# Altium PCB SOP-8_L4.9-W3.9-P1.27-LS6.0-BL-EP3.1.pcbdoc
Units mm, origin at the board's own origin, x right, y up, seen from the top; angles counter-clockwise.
Board outline 18.03 x 20.04 mm, 2 copper layers (Top Layer, Bottom Layer), stack 0 mm thick; 1 components, 0 nets, 9 pads, 4 vias.
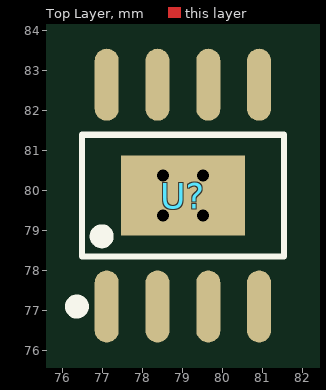
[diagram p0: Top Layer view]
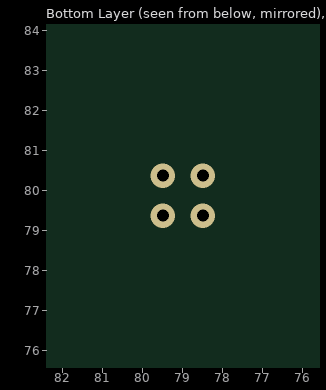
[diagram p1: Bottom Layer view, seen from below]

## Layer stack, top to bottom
Top Layer: signal copper (thickness not stored)
Bottom Layer: signal copper (thickness not stored)

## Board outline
87.878,69.85 69.85,69.85 69.85,89.895 87.878,89.895

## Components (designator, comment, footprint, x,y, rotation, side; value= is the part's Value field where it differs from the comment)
U? "" SOP-8_L4.9-W3.9-P1.27-LS6.0-BL-EP3.1 79.002,79.872 r0 top

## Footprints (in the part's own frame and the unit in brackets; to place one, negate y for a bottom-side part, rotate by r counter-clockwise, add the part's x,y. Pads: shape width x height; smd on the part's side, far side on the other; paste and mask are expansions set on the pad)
SOP-8_L4.9-W3.9-P1.27-LS6.0-BL-EP3.1 [mm]
  oval 0.6x1.8 smd: 1(-1.905,-2.772) 2(-0.635,-2.772) 3(0.635,-2.772) 4(1.905,-2.772) 5(1.905,2.772) 6(0.635,2.772) 7(-0.635,2.772) 8(-1.905,2.772)
  rect 3.1x2 smd: 9(0,0)
  silkscreen extent -2.8,-2.92 2.53,1.52

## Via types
v1: diameter 0.61, hole 0.305, Top Layer to Bottom Layer, 4 vias

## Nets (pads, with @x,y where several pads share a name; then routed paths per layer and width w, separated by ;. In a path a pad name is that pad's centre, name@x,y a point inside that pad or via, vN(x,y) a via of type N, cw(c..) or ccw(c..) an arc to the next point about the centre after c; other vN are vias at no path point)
pads on no net: U?.1 U?.2 U?.3 U?.4 U?.5 U?.6 U?.7 U?.8 U?.9
copper on no net:
  other v1: 78.502,79.372 79.502,79.372 78.502,80.372 79.502,80.372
